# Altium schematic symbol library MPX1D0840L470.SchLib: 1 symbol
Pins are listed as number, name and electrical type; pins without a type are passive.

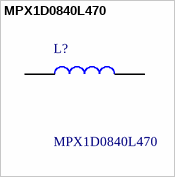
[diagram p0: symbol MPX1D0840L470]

## MPX1D0840L470
designator L?
KEMET, MPX, Power, 47 uH, 20%, 155C, -55C, 0840(3431), 2.8 A, 226.7 mOhms, 5.7 MHz, 1000, 8.65mm, 8.9mm, 8mm, 8.2mm, 4mm, 4mm
footprint INDPM8680X400N
pins: 1, 2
